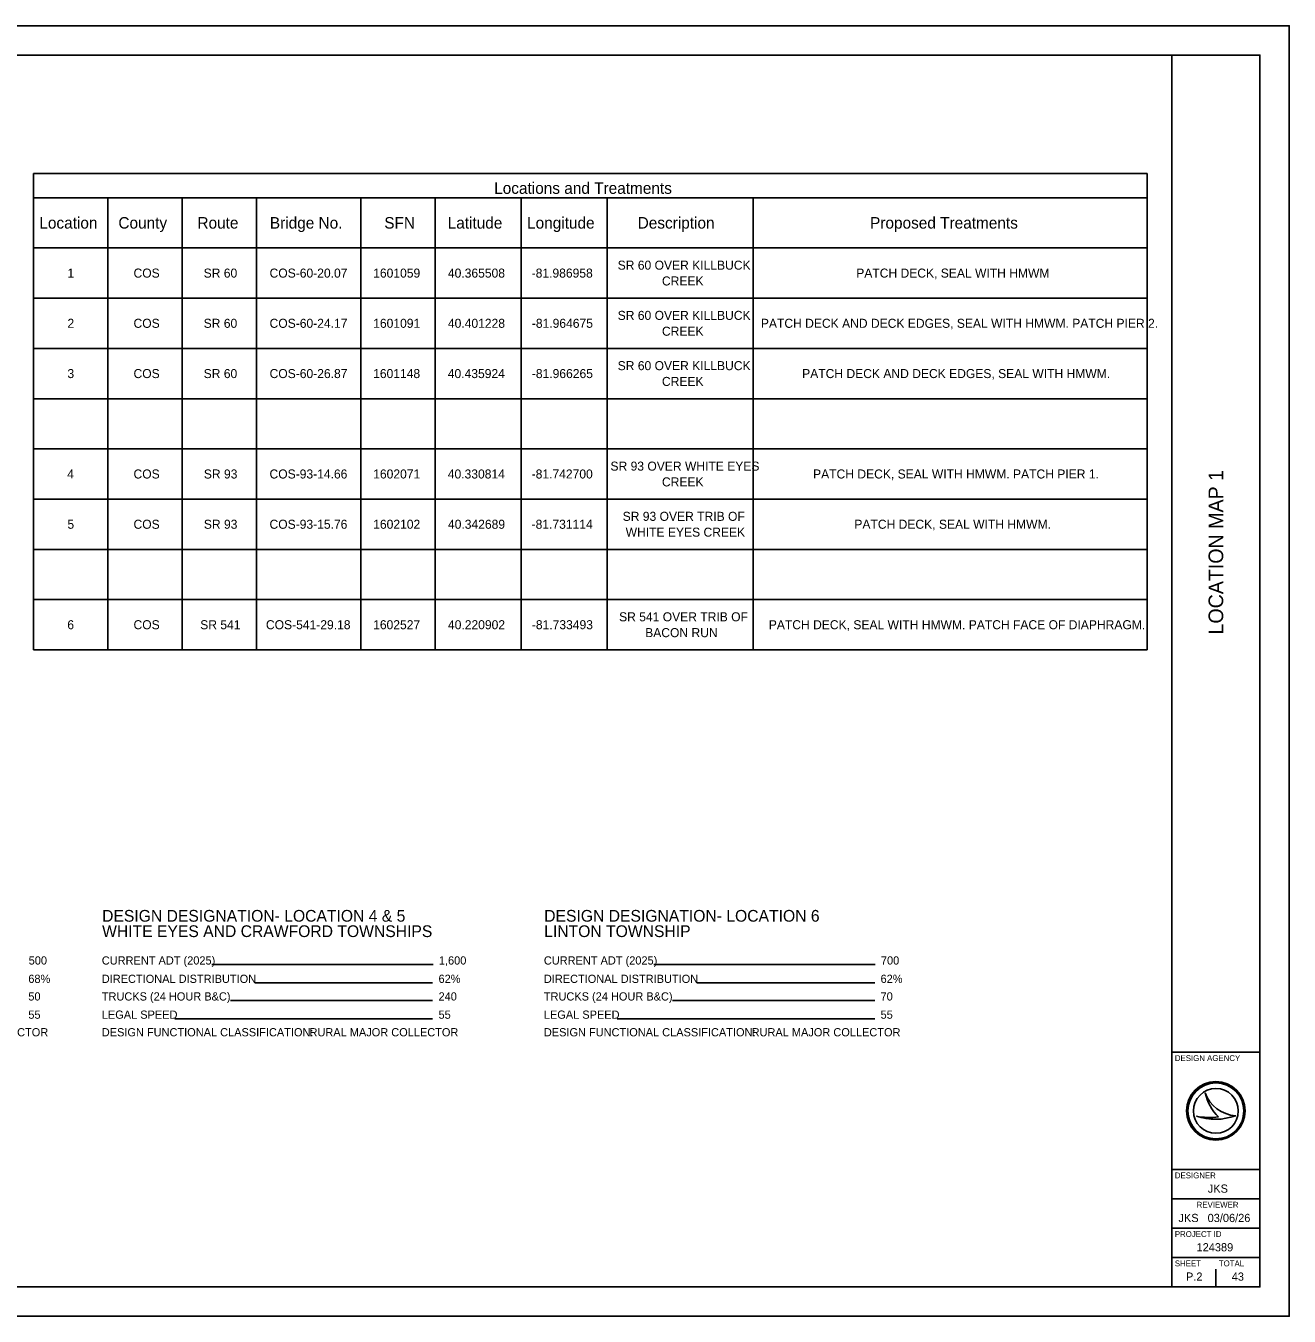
# Model space of a CAD drawing. Extents: x -6.3 to 34, y 0 to 22.
# Drawn here: x 12.46 to 34, y 0 to 22 of the extents above; entities that cross this region are included whole.
import ezdxf

# ---------------------------------------------------------------- set-up
doc = ezdxf.new("R2010")
doc.units = 0
for name, color, linetype in [('SH_Border', 7, 'Continuous'), ('SH_Cut_Line', 7, 'Continuous'), ('SH_Data', 7, 'Continuous'), ('SH_Text', 7, 'Continuous')]:
    doc.layers.add(name, color=color, linetype=linetype)

msp = doc.modelspace()

# ---------------------------------------------------------------- linework, layer by layer
at = {"layer": 'SH_Border'}
for p, q in [((32, 0.5), (32, 21.5)), ((32, 4.5), (33.5, 4.5)), ((32, 2.5), (33.5, 2.5)), ((32, 2), (33.5, 2)), ((32, 1.5), (33.5, 1.5)), ((32, 1), (33.5, 1))]:
    msp.add_line(p, q, dxfattribs=at)
msp.add_lwpolyline([(1.5, 21.5), (33.5, 21.5), (33.5, 0.5), (1.5, 0.5)], close=True, dxfattribs=at)
at = {"layer": 'SH_Cut_Line'}
msp.add_lwpolyline([(0, 0), (34, 0), (34, 22), (0, 22)], close=True, dxfattribs=at)
at = {"layer": 'SH_Data'}
for p, q in [((19.4, 5.995), (15.628, 5.995)), ((26.938, 5.995), (23.167, 5.995)), ((19.394, 5.682), (16.361, 5.682)), ((26.932, 5.682), (23.899, 5.682)), ((19.394, 5.382), (15.946, 5.382)), ((26.932, 5.382), (23.484, 5.382)), ((19.394, 5.071), (14.999, 5.071)), ((26.932, 5.071), (22.538, 5.071)), ((32.567, 3.81), (32.567, 3.81)), ((32.417, 3.41), (32.417, 3.41)), ((32.75, 3.5), (32.75, 3.5)), ((33.087, 3.419), (33.087, 3.419)), ((32.375, 0.675), (32.375, 0.675)), ((32.75, 0.5), (32.75, 0.8))]:
    msp.add_line(p, q, dxfattribs=at)
for radius in [0.5, 0.477, 0.477, 0.382]:
    msp.add_circle((32.75, 3.5), radius, dxfattribs=at)
for centre, radius, start, end in [((33.116, 3.998), 0.58, 198.9257, 198.9319), ((33.347, 3.97), 0.796, 191.6379, 191.6421), ((33.116, 3.998), 0.58, 198.9319, 267.1657), ((33.347, 3.97), 0.796, 191.6421, 226.0947), ((32.739, 4.37), 1.013, 251.4576, 290.0832), ((32.648, 4.654), 1.266, 259.4964, 259.4995), ((32.739, 4.37), 1.013, 251.4527, 251.4576), ((32.648, 4.654), 1.266, 259.4995, 276.6672)]:
    msp.add_arc(centre, radius, start, end, dxfattribs=at)
at = {"layer": 'SH_Text'}
for p, q in [((12.586, 19.481), (31.577, 19.481)), ((12.586, 19.481), (12.586, 11.361)), ((31.577, 19.481), (31.577, 11.361)), ((12.586, 19.069), (31.577, 19.069)), ((13.855, 19.069), (13.855, 11.361)), ((15.123, 19.069), (15.123, 11.361)), ((16.391, 19.069), (16.391, 11.361)), ((18.17, 19.069), (18.17, 11.361)), ((19.438, 19.069), (19.438, 11.361)), ((20.904, 19.069), (20.904, 11.361)), ((22.37, 19.069), (22.37, 11.361)), ((24.857, 19.069), (24.857, 11.361)), ((12.586, 18.213), (31.577, 18.213)), ((12.586, 17.356), (31.577, 17.356)), ((12.586, 16.5), (31.577, 16.5)), ((12.586, 15.643), (31.577, 15.643)), ((12.586, 14.787), (31.577, 14.787)), ((12.586, 13.93), (31.577, 13.93)), ((12.586, 13.074), (31.577, 13.074)), ((12.586, 12.217), (31.577, 12.217)), ((12.586, 11.361), (31.577, 11.361))]:
    msp.add_line(p, q, dxfattribs=at)

# ---------------------------------------------------------------- texts
at = {"layer": 'SH_Data'}
msp.add_text('LOCATION MAP 1', height=0.25, rotation=90, dxfattribs=at).set_placement((32.875, 11.622))
for s, height, p in [('DESIGN DESIGNATION- LOCATION 4 & 5', 0.2, (13.757, 6.726)), ('DESIGN DESIGNATION- LOCATION 6', 0.2, (21.296, 6.726)), ('WHITE EYES AND CRAWFORD TOWNSHIPS', 0.2, (13.757, 6.464)), ('LINTON TOWNSHIP', 0.2, (21.296, 6.464)), ('DESIGN AGENCY', 0.1, (32.05, 4.35)), ('DESIGNER', 0.1, (32.05, 2.35)), ('JKS', 0.14, (32.612, 2.105)), ('REVIEWER', 0.1, (32.422, 1.85)), ('JKS', 0.14, (32.112, 1.605)), ('03/06/26', 0.14, (32.609, 1.605)), ('PROJECT ID', 0.1, (32.05, 1.35)), ('124389', 0.14, (32.42, 1.105)), ('SHEET', 0.1, (32.05, 0.85)), ('TOTAL', 0.1, (32.8, 0.85)), ('P.2', 0.14, (32.24, 0.605)), ('43', 0.14, (33.02, 0.605))]:
    msp.add_text(s, height=height, dxfattribs=at).set_placement(p)
at = {"layer": 'SH_Text'}
for s, height, p in [('Locations and Treatments', 0.196, (20.443, 19.135)), ('Location', 0.196, (12.687, 18.543)), ('County', 0.196, (14.035, 18.543)), ('Route', 0.196, (15.383, 18.543)), ('Bridge No.', 0.196, (16.618, 18.543)), ('SFN', 0.196, (18.569, 18.543)), ('Latitude', 0.196, (19.65, 18.543)), ('Longitude', 0.196, (21.004, 18.543)), ('Description', 0.196, (22.89, 18.543)), ('Proposed Treatments', 0.196, (26.853, 18.543)), ('1', 0.154, (13.166, 17.707)), ('COS', 0.154, (14.293, 17.707)), ('SR 60', 0.154, (15.489, 17.707)), ('COS-60-20.07', 0.154, (16.613, 17.707)), ('1601059', 0.154, (18.38, 17.707)), ('40.365508', 0.154, (19.654, 17.707)), ('-81.986958', 0.154, (21.082, 17.707)), ('SR 60 OVER KILLBUCK ', 0.154, (22.549, 17.842)), ('PATCH DECK, SEAL WITH HMWM', 0.154, (26.617, 17.707)), ('CREEK', 0.154, (23.304, 17.573)), ('2', 0.154, (13.166, 16.851)), ('COS', 0.154, (14.293, 16.851)), ('SR 60', 0.154, (15.489, 16.851)), ('COS-60-24.17', 0.154, (16.613, 16.851)), ('1601091', 0.154, (18.38, 16.851)), ('40.401228', 0.154, (19.654, 16.851)), ('-81.964675', 0.154, (21.085, 16.851)), ('SR 60 OVER KILLBUCK ', 0.154, (22.549, 16.986)), ('PATCH DECK AND DECK EDGES, SEAL WITH HMWM. PATCH PIER 2.', 0.154, (24.991, 16.851)), ('CREEK', 0.154, (23.304, 16.716)), ('SR 60 OVER KILLBUCK ', 0.154, (22.549, 16.129)), ('3', 0.154, (13.166, 15.994)), ('COS', 0.154, (14.293, 15.994)), ('SR 60', 0.154, (15.489, 15.994)), ('COS-60-26.87', 0.154, (16.613, 15.994)), ('1601148', 0.154, (18.379, 15.994)), ('40.435924', 0.154, (19.652, 15.994)), ('-81.966265', 0.154, (21.085, 15.994)), ('PATCH DECK AND DECK EDGES, SEAL WITH HMWM.', 0.154, (25.695, 15.994)), ('CREEK', 0.154, (23.304, 15.86)), ('SR 93 OVER WHITE EYES ', 0.154, (22.426, 14.416)), ('4', 0.154, (13.162, 14.282)), ('COS', 0.154, (14.293, 14.282)), ('SR 93', 0.154, (15.492, 14.282)), ('COS-93-14.66', 0.154, (16.612, 14.282)), ('1602071', 0.154, (18.38, 14.282)), ('40.330814', 0.154, (19.652, 14.282)), ('-81.742700', 0.154, (21.082, 14.282)), ('CREEK', 0.154, (23.304, 14.147)), ('PATCH DECK, SEAL WITH HMWM. PATCH PIER 1.', 0.154, (25.881, 14.282)), ('SR 93 OVER TRIB OF ', 0.154, (22.634, 13.56)), ('5', 0.154, (13.166, 13.425)), ('COS', 0.154, (14.293, 13.425)), ('SR 93', 0.154, (15.492, 13.425)), ('COS-93-15.76', 0.154, (16.612, 13.425)), ('1602102', 0.154, (18.38, 13.425)), ('40.342689', 0.154, (19.655, 13.425)), ('-81.731114', 0.154, (21.081, 13.425)), ('WHITE EYES CREEK', 0.154, (22.685, 13.29)), ('PATCH DECK, SEAL WITH HMWM.', 0.154, (26.585, 13.425)), ('SR 541 OVER TRIB OF ', 0.154, (22.573, 11.847)), ('6', 0.154, (13.164, 11.712)), ('COS', 0.154, (14.293, 11.712)), ('SR 541', 0.154, (15.43, 11.712)), ('COS-541-29.18', 0.154, (16.551, 11.712)), ('1602527', 0.154, (18.379, 11.712)), ('40.220902', 0.154, (19.655, 11.712)), ('-81.733493', 0.154, (21.085, 11.712)), ('BACON RUN', 0.154, (23.018, 11.577)), ('PATCH DECK, SEAL WITH HMWM. PATCH FACE OF DIAPHRAGM.', 0.154, (25.126, 11.712)), ('500', 0.14, (12.505, 5.995)), ('CURRENT ADT (2025)', 0.14, (13.752, 5.995)), ('1,600', 0.14, (19.5, 5.995)), ('CURRENT ADT (2025)', 0.14, (21.29, 5.995)), ('700', 0.14, (27.038, 5.995)), ('68%', 0.14, (12.499, 5.682)), ('DIRECTIONAL DISTRIBUTION', 0.14, (13.752, 5.682)), ('62%', 0.14, (19.494, 5.682)), ('DIRECTIONAL DISTRIBUTION', 0.14, (21.29, 5.682)), ('62%', 0.14, (27.032, 5.682)), ('50', 0.14, (12.499, 5.382)), ('TRUCKS (24 HOUR B&C)', 0.14, (13.752, 5.382)), ('240', 0.14, (19.494, 5.382)), ('TRUCKS (24 HOUR B&C)', 0.14, (21.29, 5.382)), ('70', 0.14, (27.032, 5.382)), ('55', 0.14, (12.499, 5.071)), ('LEGAL SPEED', 0.14, (13.752, 5.071)), ('55', 0.14, (19.494, 5.071)), ('LEGAL SPEED', 0.14, (21.29, 5.071)), ('55', 0.14, (27.032, 5.071)), ('RURAL MAJOR COLLECTOR', 0.14, (10.3, 4.771)), ('DESIGN FUNCTIONAL CLASSIFICATION:', 0.14, (13.752, 4.771)), ('RURAL MAJOR COLLECTOR', 0.14, (17.294, 4.771)), ('DESIGN FUNCTIONAL CLASSIFICATION:', 0.14, (21.29, 4.771)), ('RURAL MAJOR COLLECTOR', 0.14, (24.833, 4.771))]:
    msp.add_text(s, height=height, dxfattribs=at).set_placement(p)

doc.saveas('drawing.dxf')
